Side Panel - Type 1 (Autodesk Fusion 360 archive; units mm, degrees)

design "Side Panel - Type 1" references "Creating Pin Holes"
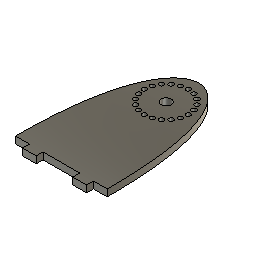
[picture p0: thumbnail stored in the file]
parameter "Length_X" = 200
parameter "Length_Y" = 300
parameter "HL_X" = 100 (= "Length_X / 2")
parameter "Hole_Diam" = 22
parameter "Hole_Hight_Y" = 229 (= "Length_Y - Hole_Diam / 2 - 0.2 * Length_Y")
parameter "Length_Z" = 15 comment "width of the wood used"
parameter "Dis_X" = 30 comment "Sitance frome the Side, X-axis"
parameter "Pin" = 30 comment "Length of pin"
parameter "Pin_H" = 15 (= "Length_Z")
sketch "Sketch1" plane through (0, 0, 0) normal (0, 0, 1) x axis (1, 0, 0)
  line L1 (-200, 0) -> (0, 0)
  curve K1 (0, 0) -> (-200, 0)
  curve K2 (0, -70) -> (0, 70)
  curve K3 (-200, 70) -> (-200, -70)
  circle C1 centre (-100, 229) radius 11
  point P1 (0, 0)
  point P2 (0, 0)
  point P4 (-100, 0)
  point P5 (-100, 300)
  point P6 (-100, 300)
  point P7 (-100, 229)
  point P3 (-200, 0)
  point P8 (0, 70)
  point P11 (-200, 70)
  coincident P1 P2
  horizontal L1
  coincident L1 P4
  vertical P4 P5
  coincident P5 P6
  vertical P4 P7
  midpoint P2 K2
  midpoint P3 K3
  horizontal P8 P11
  dimension "d4" distance P2 P3 = 200 (= "Length_X")
  dimension "d5" distance P1 P4 = 100 (= "HL_X")
  dimension "d6" distance P4 P5 = 300 (= "Length_Y")
  dimension "d8" diameter C1 = 22 (= "Hole_Diam")
  dimension "d10" distance P4 P7 = 229 (= "Hole_Hight_Y")
extrude "Extrude1" new body sketch "Sketch1" profile of L1 K1 C1 along normal blind 15 (= "Length_Z")
component_insert "Component Insert"
joint "Assemble1" alignAngle 0 alignOffsetY 229 (= "Hole_Hight_Y") alignOffsetZ 0
combine "Combine1"
sketch "Sketch2" plane through (0, 0, 0) normal (0, -1, 0) x axis (1, 0, 0)
  line L1 (0, 0) -> (-200, 0)
  line L2 (0, 15) -> (0, 0)
  line L3 (-200, 15) -> (0, 15)
  line L4 (-200, 0) -> (-200, 15)
  line L5 (-60, 0) -> (-30, 0)
  line L6 (-60, 15) -> (-60, 0)
  line L7 (-30, 15) -> (-60, 15)
  line L8 (-30, 0) -> (-30, 15)
  line L9 (-140, 0) -> (-170, 0)
  line L10 (-140, 15) -> (-140, 0)
  line L11 (-170, 15) -> (-140, 15)
  line L12 (-170, 0) -> (-170, 15)
  point P6 (-30, 0)
  point P12 (-140, 15)
  point P10 (-170, 0)
  point P1 (0, 0)
  point P8 (-60, 15)
  point P9 (-30, 15)
  point P2 (-200, 0)
  point P13 (-170, 15)
  horizontal L5
  vertical L6
  horizontal L7
  vertical L8
  coincident L1 P6
  horizontal L9
  vertical L10
  horizontal L11
  vertical L12
  coincident L3 P12
  coincident L1 P10
  dimension "d20" distance P1 P6 = 30 (= "Dis_X")
  dimension "d21" distance P8 P9 = 30 (= "Pin")
  dimension "d22" distance P6 P9 = 15 (= "Length_Z")
  dimension "d23" distance P2 P10 = 30 (= "Dis_X")
  dimension "d24" distance P12 P13 = 30 (= "Pin")
extrude "Extrude2" add sketch "Sketch2" profile of L1 L3 L5 L6 L7 L8 L9 L10 L11 L12 along normal blind 15 (= "Pin_H")
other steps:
joint_origin "JointOrigin2"

design "Creating Pin Holes"
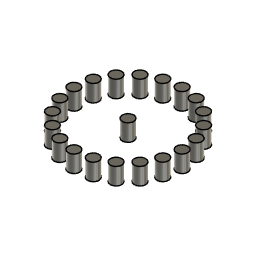
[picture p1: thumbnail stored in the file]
parameter "Diameter" = 10
parameter "Higth" = 15
parameter "Ss" = 15 (= "Diameter * 1.5")
parameter "Circumcircle_R" = 47.9434 (= "Ss / ( 2 * sin(( 180 / n ) * 1 deg) )")
sketch "Sketch1" plane through (0, 0, 0) normal (0, 0, 1) x axis (1, 0, 0)
  circle C1 centre (0, 47.9434) radius 5
  point P1 (0, 0)
  point P2 (0, 47.9434)
  vertical P1 P2
  dimension "d7" diameter C1 = 10 (= "Diameter")
  dimension "d12" distance P1 P2 = 47.9434 (= "Circumcircle_R")
extrude "Extrude1" new body sketch "Sketch1" along normal blind 15 (= "Higth")
circular_pattern "C-Pattern1" TotalAngle 360
sketch "Sketch2" plane through (0, 0, 0) normal (0, 0, 1) x axis (1, 0, 0)
  circle C1 centre (0, 0) radius 5
  point P1 (0, 0)
  point P2 (0, 0)
  coincident P1 P2
  dimension "d13" diameter C1 = 10 (= "Diameter")
extrude "Extrude2" new body sketch "Sketch2" along normal blind 15 (= "Higth")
